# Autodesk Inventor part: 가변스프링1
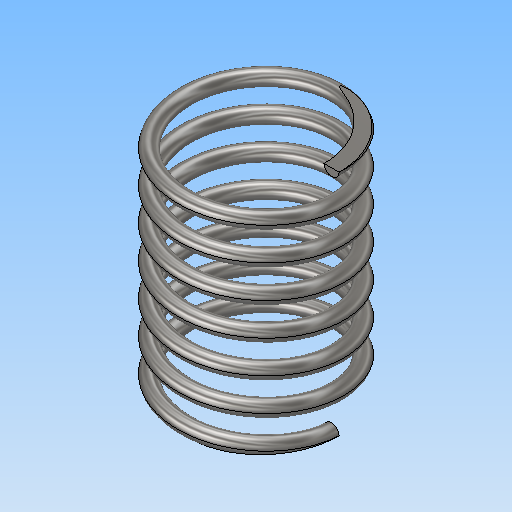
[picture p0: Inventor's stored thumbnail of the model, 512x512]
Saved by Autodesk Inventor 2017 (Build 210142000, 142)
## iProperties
Part Number: 가변스프링1
Material: 스테인레스 스틸
Document SubType Name: Modeling
Designer: MRC
Density: 8 g/cm^3
Appearance: 반연마
Mass: 10.9002 g
Surface Area: 27.5826 cm^2
Volume: 1.36253 cm^3
Author: MRC
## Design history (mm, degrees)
sketch "스케치1"
  geometry: L1 (0, 0)-(10, 0); L2 (10, 0)-(10, 30.208); L3 (10, 30.208)-(0, 30.208); L4 (0, 30.208)-(0, 0); C1 r 1 at (10, 0)
  constraints: 8 end point, 2 parallel, 1 centre point, 1 coincident, 1 horizontal, 1 perpendicular
  dimensions: "d0" = 30.20829 distance between parallel lines of L1 L3 (derived); "d1" = 20 diameter of L2 L4; "d2" = 2 diameter of C1
feature "코일1" sketch "스케치1" pitch "d3" = 10; turns "d5" = 7; dims "d4" = 30.20829 (= d0), "d6" = 0, angle "d7" = 90 deg, angle "d8" = 90 deg, "d9" = 0, "d10" = 0
sketch "스케치2"
  geometry: L1 (0, -17.9)-(30.208, -17.9); L2 (30.208, -17.9)-(30.208, 17.9); L3 (30.208, 17.9)-(0, 17.9); L4 (0, 17.9)-(0, -17.9); 4 further points
  constraints: 8 end point, 2 coincident, 2 midpoint, 2 parallel, 1 horizontal, 1 perpendicular
  dimensions: "d11" = 35.80033 distance between parallel lines of L1 L3
extrude "돌출1" sketch "스케치2" stored distance "d12" = 50; taper "d13" = 0 deg
node "솔리드1"
